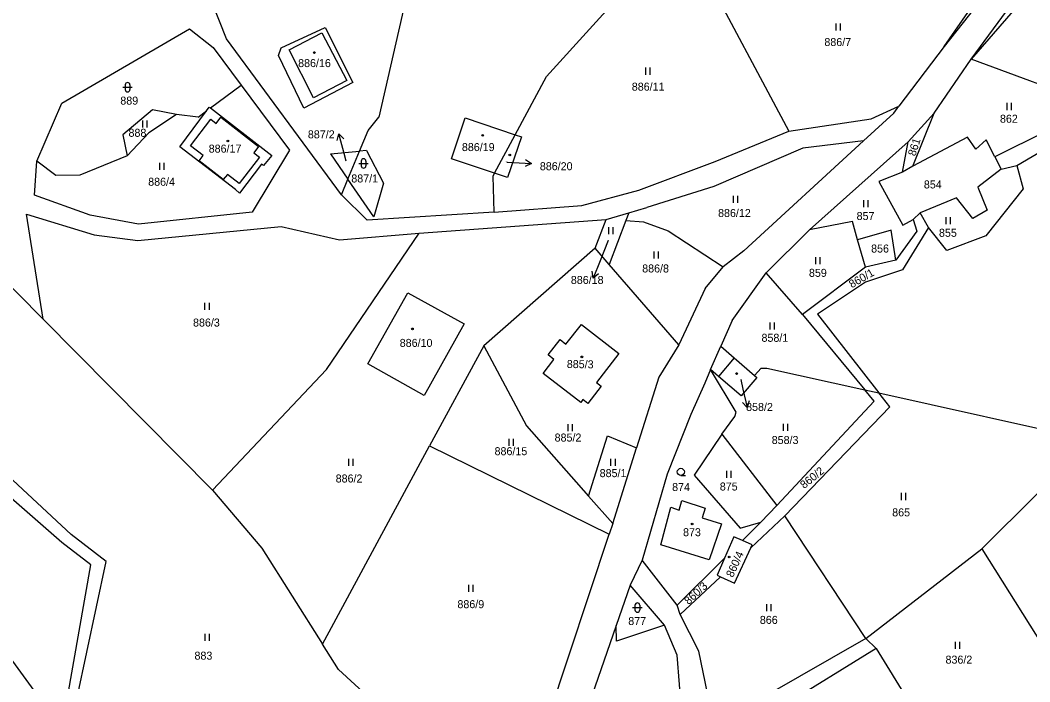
# Model space of a CAD drawing. Extents: x -670359 to -668019, y -978807 to -976674.
# Drawn here: x -669351.9 to -669137.4, y -977619.9 to -977479.4 of the extents above; entities that cross this region are included whole.
import ezdxf

# ---------------------------------------------------------------- set-up
doc = ezdxf.new("R2010")
doc.units = 0
for name, color, linetype in [('Hranice parcel', 7, 'Continuous'), ('Parcelní čísla', 7, 'Continuous'), ('Vnitřní kresba', 7, 'Continuous'), ('Značky budov', 7, 'Continuous'), ('Značky kultur', 7, 'Continuous')]:
    doc.layers.add(name, color=color, linetype=linetype)

msp = doc.modelspace()

# ---------------------------------------------------------------- linework, layer by layer
at = {"layer": 'Hranice parcel'}
for p, q in [((-669296.47, -977485.29), (-669287.14, -977480.93)), ((-669287.14, -977480.93), (-669281.27, -977492.61)), ((-669297.06, -977486.92), (-669296.47, -977485.29)), ((-669291.64, -977498.08), (-669297.06, -977486.92)), ((-669281.27, -977492.61), (-669291.64, -977498.08))]:
    msp.add_line(p, q, dxfattribs=at)
for points in [[(-669108.16, -977439.61), (-669149.88, -977487.66)], [(-669262.21, -977440.81), (-669275.7, -977499.98)], [(-669308.09, -977483.36), (-669317, -977460.78)], [(-669240.07, -977491.32), (-669212, -977460.35)], [(-669155.63, -977485.01), (-669142.12, -977465.6)], [(-669149.88, -977487.66), (-669133.84, -977465.83)], [(-669207.54, -977467.5), (-669188.62, -977502.97)], [(-669141.64, -977467.28), (-669155.63, -977485.01)], [(-669343.06, -977497.02), (-669315.95, -977481.19)], [(-669315.95, -977481.19), (-669310.92, -977485.22)], [(-669310.92, -977485.22), (-669305, -977493.18)], [(-669283.67, -977516.5), (-669308.09, -977483.36)], [(-669155.63, -977485.01), (-669165.21, -977497.66)], [(-669157.76, -977499.16), (-669149.88, -977487.66)], [(-669123.01, -977497.58), (-669149.88, -977487.66)], [(-669246.73, -977503.74), (-669240.07, -977491.32)], [(-669311.5, -977498.03), (-669305, -977493.18)], [(-669305, -977493.18), (-669294.73, -977507.01)], [(-669348.43, -977509.36), (-669343.06, -977497.02)], [(-669312.36, -977498.67), (-669311.75, -977497.84)], [(-669311.75, -977497.84), (-669311.5, -977498.03)], [(-669311.5, -977498.03), (-669298.5, -977508.1)], [(-669171.1, -977500.35), (-669165.21, -977497.66)], [(-669166.33, -977499.14), (-669165.21, -977497.66)], [(-669123.01, -977497.58), (-669144.82, -977508.4)], [(-669323.85, -977498.42), (-669330.14, -977503.73)], [(-669318.73, -977499.43), (-669324.63, -977503.3)], [(-669318.73, -977499.43), (-669323.85, -977498.42)], [(-669314.09, -977499.96), (-669318.73, -977499.43)], [(-669317.98, -977506.3), (-669312.36, -977498.67)], [(-669314.09, -977499.96), (-669312.36, -977498.67)], [(-669278.01, -977502.82), (-669275.7, -977499.98)], [(-669251.12, -977511.91), (-669260.28, -977508.84), (-669257.36, -977500.15)], [(-669257.36, -977500.15), (-669246.73, -977503.74)], [(-669166.33, -977499.14), (-669172.75, -977505.05)], [(-669163.23, -977505.23), (-669157.76, -977499.16)], [(-669162.29, -977510.43), (-669157.76, -977499.16)], [(-669140.19, -977510.25), (-669123.02, -977500.22)], [(-669188.62, -977502.97), (-669171.1, -977500.35)], [(-669330.14, -977503.73), (-669329.24, -977508.2)], [(-669324.63, -977503.3), (-669329.24, -977508.2)], [(-669279.84, -977507.23), (-669278.01, -977502.82)], [(-669251.12, -977511.91), (-669246.73, -977503.74)], [(-669246.73, -977503.74), (-669245.43, -977504.18), (-669248.36, -977512.84), (-669251.12, -977511.91)], [(-669204.3, -977509.42), (-669188.62, -977502.97)], [(-669150.65, -977504.22), (-669162.29, -977510.43)], [(-669148.9, -977506.79), (-669150.65, -977504.22)], [(-669306.22, -977515.38), (-669317.98, -977506.3)], [(-669185.65, -977506.58), (-669204.54, -977514.75)], [(-669198.14, -977528.41), (-669172.75, -977505.05)], [(-669172.75, -977505.05), (-669185.65, -977506.58)], [(-669184.19, -977523.89), (-669163.23, -977505.23)], [(-669164.45, -977511.7), (-669163.23, -977505.23)], [(-669146.65, -977504.79), (-669148.9, -977506.79)], [(-669144.82, -977508.4), (-669146.65, -977504.79)], [(-669329.24, -977508.2), (-669339.29, -977512.34)], [(-669294.73, -977507.01), (-669302.62, -977520.16)], [(-669298.5, -977508.1), (-669300.25, -977510.28)], [(-669285.98, -977507.78), (-669279.84, -977507.23)], [(-669285.98, -977507.78), (-669282.29, -977513.15)], [(-669282.29, -977513.15), (-669279.84, -977507.23)], [(-669278.38, -977507.1), (-669279.84, -977507.23)], [(-669278.38, -977507.1), (-669274.75, -977514.03)], [(-669144.82, -977508.4), (-669143.47, -977511.04)], [(-669348.91, -977516.54), (-669348.43, -977509.36)], [(-669344.33, -977512.37), (-669348.43, -977509.36)], [(-669300.64, -977509.97), (-669305.35, -977516.1)], [(-669300.25, -977510.28), (-669300.64, -977509.97)], [(-669220.45, -977515.51), (-669204.3, -977509.42)], [(-669162.29, -977510.43), (-669164.45, -977511.7)], [(-669143.47, -977511.04), (-669148.45, -977514.87)], [(-669143.47, -977511.04), (-669140.19, -977510.25)], [(-669140.19, -977510.25), (-669138.84, -977515.22)], [(-669339.29, -977512.34), (-669344.33, -977512.37)], [(-669283.67, -977516.5), (-669282.29, -977513.15)], [(-669276.79, -977521.15), (-669282.29, -977513.15)], [(-669251.43, -977512.49), (-669251.12, -977511.91)], [(-669251.24, -977520.17), (-669251.43, -977512.49)], [(-669164.45, -977511.7), (-669169.5, -977513.69)], [(-669274.75, -977514.03), (-669276.79, -977521.15)], [(-669204.54, -977514.75), (-669218.8, -977519.2)], [(-669169.5, -977513.69), (-669164.41, -977522.91)], [(-669148.45, -977514.87), (-669146.46, -977519.76)], [(-669138.84, -977515.22), (-669146.72, -977525.19)], [(-669337.08, -977520.79), (-669348.91, -977516.54)], [(-669305.35, -977516.1), (-669306.22, -977515.38)], [(-669278.22, -977521.9), (-669283.67, -977516.5)], [(-669232.6, -977518.73), (-669220.45, -977515.51)], [(-669153.02, -977517.1), (-669160.72, -977520.28)], [(-669149.51, -977521.51), (-669153.02, -977517.1)], [(-669251.24, -977520.17), (-669232.6, -977518.73)], [(-669222.6, -977520.3), (-669218.8, -977519.2)], [(-669347.06, -977542.92), (-669350.57, -977520.6)], [(-669350.57, -977520.6), (-669336.25, -977524.95)], [(-669326.83, -977522.73), (-669337.08, -977520.79)], [(-669302.62, -977520.16), (-669326.83, -977522.73)], [(-669251.24, -977520.17), (-669278.22, -977521.9)], [(-669267.17, -977524.66), (-669227.45, -977521.71)], [(-669229.76, -977527.85), (-669227.45, -977521.71)], [(-669227.45, -977521.71), (-669222.6, -977520.3)], [(-669222.6, -977520.3), (-669223.23, -977521.96)], [(-669164.41, -977522.91), (-669162.16, -977521.71)], [(-669160.72, -977520.28), (-669162.16, -977521.71)], [(-669162.16, -977521.71), (-669161.45, -977524.19)], [(-669158.97, -977523.4), (-669160.72, -977520.28)], [(-669146.46, -977519.76), (-669149.51, -977521.51)], [(-669326.97, -977526.2), (-669296.46, -977523.22)], [(-669296.46, -977523.22), (-669284.09, -977526.07)], [(-669223.23, -977521.96), (-669226.76, -977531.31)], [(-669223.23, -977521.96), (-669219.49, -977522.19)], [(-669219.49, -977522.19), (-669214.23, -977524.13)], [(-669193.43, -977533.07), (-669184.19, -977523.89)], [(-669175.05, -977522.16), (-669184.19, -977523.89)], [(-669174.03, -977526.08), (-669175.05, -977522.16)], [(-669158.97, -977523.4), (-669164.44, -977532.43)], [(-669155.06, -977528.29), (-669158.97, -977523.4)], [(-669336.25, -977524.95), (-669326.97, -977526.2)], [(-669286.84, -977553.62), (-669267.17, -977524.66)], [(-669284.09, -977526.07), (-669267.17, -977524.66)], [(-669214.23, -977524.13), (-669202.58, -977531.77)], [(-669166.89, -977524.02), (-669174.03, -977526.08)], [(-669165.87, -977530.34), (-669166.89, -977524.02)], [(-669161.45, -977524.19), (-669165.87, -977530.34)], [(-669146.72, -977525.19), (-669155.06, -977528.29)], [(-669363.13, -977526.7), (-669347.06, -977542.92)], [(-669229.76, -977527.85), (-669253.45, -977548.58)], [(-669226.76, -977531.31), (-669229.76, -977527.85)], [(-669172.29, -977531.84), (-669174.03, -977526.08)], [(-669198.14, -977528.41), (-669202.58, -977531.77)], [(-669165.87, -977530.34), (-669172.29, -977531.84)], [(-669211.97, -977548.38), (-669226.76, -977531.31)], [(-669206.41, -977536.39), (-669202.58, -977531.77)], [(-669172.29, -977531.84), (-669185.69, -977541.89)], [(-669164.44, -977532.43), (-669172.3, -977535.05)], [(-669200.67, -977543.21), (-669193.43, -977533.07)], [(-669185.69, -977541.89), (-669193.43, -977533.07)], [(-669206.41, -977536.39), (-669211.97, -977548.38)], [(-669172.3, -977535.05), (-669182.49, -977541.82)], [(-669278.06, -977552.4), (-669269.59, -977537.3)], [(-669269.59, -977537.3), (-669257.59, -977543.88)], [(-669311.1, -977579.22), (-669347.06, -977542.92)], [(-669200.67, -977543.21), (-669203.09, -977548.67)], [(-669185.69, -977541.89), (-669172.45, -977557.92)], [(-669182.49, -977541.82), (-669169.48, -977558.58)], [(-669257.59, -977543.88), (-669266.13, -977559.09)], [(-669236.01, -977548.19), (-669232.68, -977544.03)], [(-669232.68, -977544.03), (-669224.77, -977550.2)], [(-669239.77, -977550.48), (-669237.18, -977547.25)], [(-669237.18, -977547.25), (-669236.01, -977548.19)], [(-669253.45, -977548.58), (-669264.94, -977569.83)], [(-669253.45, -977548.58), (-669244.38, -977565.57)], [(-669211.97, -977548.38), (-669216.24, -977555.25)], [(-669205.27, -977553.6), (-669203.09, -977548.67)], [(-669203.09, -977548.67), (-669200.23, -977551.14)], [(-669240.79, -977554.44), (-669238.57, -977551.46)], [(-669238.57, -977551.46), (-669239.77, -977550.48)], [(-669224.77, -977550.2), (-669229.47, -977556.38)], [(-669200.23, -977551.14), (-669195.88, -977554.9)], [(-669311.1, -977579.22), (-669286.84, -977553.62)], [(-669266.13, -977559.09), (-669278.06, -977552.4)], [(-669205.27, -977553.6), (-669206.44, -977556.51)], [(-669199.77, -977562.65), (-669205.27, -977553.6)], [(-669203.55, -977555.07), (-669205.27, -977553.6)], [(-669195.88, -977554.9), (-669194.52, -977553.32)], [(-669194.52, -977553.32), (-669193.32, -977553.28)], [(-669193.32, -977553.28), (-669172.45, -977557.92)], [(-669232.83, -977560.61), (-669240.79, -977554.44)], [(-669216.24, -977555.25), (-669220.95, -977570.21)], [(-669198.76, -977559.21), (-669203.55, -977555.07)], [(-669195.4, -977555.31), (-669198.76, -977559.21)], [(-669195.88, -977554.9), (-669195.4, -977555.31)], [(-669228.49, -977557.16), (-669231.31, -977560.8)], [(-669229.47, -977556.38), (-669228.49, -977557.16)], [(-669206.44, -977556.51), (-669209.46, -977563.18)], [(-669170.46, -977560.33), (-669172.45, -977557.92)], [(-669172.45, -977557.92), (-669169.48, -977558.58)], [(-669232.36, -977559.99), (-669232.83, -977560.61)], [(-669231.31, -977560.8), (-669232.36, -977559.99)], [(-669191.19, -977582.52), (-669170.46, -977560.33)], [(-669167.18, -977561.54), (-669169.48, -977558.58)], [(-669169.48, -977558.58), (-669124.36, -977568.61)], [(-669167.18, -977561.54), (-669189.44, -977584.68)], [(-669341.12, -977588.67), (-669368.05, -977563.65)], [(-669209.46, -977563.18), (-669214.43, -977575.81)], [(-669202.83, -977567.36), (-669200.09, -977563.61)], [(-669200.09, -977563.61), (-669199.77, -977562.65)], [(-669343.11, -977590.36), (-669370.27, -977566.62)], [(-669244.38, -977565.57), (-669231.17, -977580.52)], [(-669231.17, -977580.52), (-669227.16, -977567.67)], [(-669227.16, -977567.67), (-669220.95, -977570.21)], [(-669202.83, -977567.36), (-669208.7, -977576.07)], [(-669202.83, -977567.36), (-669191.19, -977582.52)], [(-669147.59, -977591.68), (-669124.36, -977568.61)], [(-669287.69, -977611.91), (-669264.94, -977569.83)], [(-669264.94, -977569.83), (-669226.78, -977588.58)], [(-669226.03, -977586.34), (-669220.95, -977570.21)], [(-669214.43, -977575.81), (-669219.81, -977594.12)], [(-669208.7, -977576.07), (-669198.97, -977587.3)], [(-669311.1, -977579.22), (-669300.56, -977591.54)], [(-669226.03, -977586.34), (-669231.17, -977580.52)], [(-669211.93, -977583.5), (-669211.36, -977581.42)], [(-669211.36, -977581.42), (-669206.41, -977583.04)], [(-669215.8, -977590.85), (-669213.69, -977582.85)], [(-669213.69, -977582.85), (-669211.93, -977583.5)], [(-669206.41, -977583.04), (-669207.05, -977585.11)], [(-669194.57, -977586.03), (-669191.19, -977582.52)], [(-669207.05, -977585.11), (-669202.89, -977586.41)], [(-669198.97, -977587.3), (-669194.57, -977586.03)], [(-669194.57, -977586.03), (-669198.48, -977589.92)], [(-669189.44, -977584.68), (-669196.67, -977591.5)], [(-669172.23, -977610.73), (-669189.44, -977584.68)], [(-669226.03, -977586.34), (-669226.78, -977588.58)], [(-669202.89, -977586.41), (-669205.56, -977594)], [(-669336.93, -977595.11), (-669343.11, -977590.36)], [(-669333.65, -977594.37), (-669341.12, -977588.67)], [(-669239.62, -977627.27), (-669226.78, -977588.58)], [(-669200.29, -977589.11), (-669202.28, -977593.69)], [(-669198.48, -977589.92), (-669200.29, -977589.11)], [(-669196.37, -977590.86), (-669198.48, -977589.92)], [(-669300.56, -977591.54), (-669287.69, -977611.91)], [(-669205.56, -977594), (-669215.8, -977590.85)], [(-669200.17, -977599.01), (-669196.67, -977591.5)], [(-669196.67, -977591.5), (-669196.37, -977590.86)], [(-669172.23, -977610.73), (-669147.59, -977591.68)], [(-669147.59, -977591.68), (-669130.3, -977619.14)], [(-669339.81, -977623.26), (-669333.65, -977594.37)], [(-669219.81, -977594.12), (-669222.31, -977599.39)], [(-669212.32, -977603.66), (-669219.81, -977594.12)], [(-669202.28, -977593.69), (-669212.32, -977603.66)], [(-669202.28, -977593.69), (-669203.85, -977597.29)], [(-669347.25, -977624.1), (-669368.28, -977595.3)], [(-669341.89, -977623.27), (-669336.93, -977595.11)], [(-669203.16, -977597.61), (-669211.69, -977605.66)], [(-669203.85, -977597.29), (-669203.16, -977597.61)], [(-669203.16, -977597.61), (-669200.17, -977599.01)], [(-669222.31, -977599.39), (-669225.3, -977607.95)], [(-669215.06, -977607.89), (-669222.31, -977599.39)], [(-669211.69, -977605.66), (-669212.32, -977603.66)], [(-669207.71, -977613.43), (-669211.69, -977605.66)], [(-669225.3, -977607.95), (-669231.13, -977624.73)], [(-669225.24, -977611.31), (-669225.3, -977607.95)], [(-669215.06, -977607.89), (-669225.24, -977611.31)], [(-669212.35, -977614.3), (-669215.06, -977607.89)], [(-669172.23, -977610.73), (-669193.64, -977623)], [(-669172.23, -977610.73), (-669170.07, -977612.9)], [(-669284.27, -977617.33), (-669287.69, -977611.91)], [(-669204.48, -977629.2), (-669207.71, -977613.43)], [(-669170.07, -977612.9), (-669190.21, -977625.32)], [(-669170.07, -977612.9), (-669156.04, -977635.66)], [(-669210.82, -977632.95), (-669212.35, -977614.3)], [(-669284.27, -977617.33), (-669272.21, -977628.45)]]:
    msp.add_lwpolyline(points, dxfattribs=at)
at = {"layer": 'Parcelní čísla'}
for p, q in [((-669284.59, -977504.97), (-669284.2, -977503.52)), ((-669282.68, -977509.3), (-669283.18, -977507.39)), ((-669248.54, -977509.57), (-669247.29, -977509.63)), ((-669244.56, -977509), (-669243.29, -977509.8)), ((-669227.01, -977526.16), (-669228.73, -977530.48)), ((-669229.03, -977533.27), (-669230.2, -977534.2)), ((-669198.83, -977555.7), (-669198.36, -977557.78)), ((-669197.03, -977560.25), (-669197.47, -977561.68))]:
    msp.add_line(p, q, dxfattribs=at)
for points in [[(-669283.18, -977507.39), (-669284.2, -977503.52), (-669283.14, -977504.59)], [(-669247.29, -977509.63), (-669243.29, -977509.8), (-669244.62, -977510.5)], [(-669228.73, -977530.48), (-669230.2, -977534.2), (-669230.42, -977532.71)], [(-669198.36, -977557.78), (-669197.47, -977561.68), (-669198.49, -977560.58)]]:
    msp.add_lwpolyline(points, dxfattribs=at)
at = {"layer": 'Vnitřní kresba'}
for p, q in [((-669294.77, -977485.67), (-669287.81, -977482.08)), ((-669287.81, -977482.08), (-669282.5, -977492.21)), ((-669289.59, -977495.88), (-669294.77, -977485.67)), ((-669282.5, -977492.21), (-669289.59, -977495.88))]:
    msp.add_line(p, q, dxfattribs=at)
for points in [[(-669310.3, -977501.32), (-669309.3, -977500.02)], [(-669309.3, -977500.02), (-669301.3, -977506.22)], [(-669315.78, -977506.05), (-669311.46, -977500.43)], [(-669311.46, -977500.43), (-669310.3, -977501.32)], [(-669313.04, -977508.15), (-669315.78, -977506.05)], [(-669301.3, -977506.22), (-669302.3, -977507.56)], [(-669313.88, -977509.25), (-669313.04, -977508.15)], [(-669301.08, -977508.47), (-669305.42, -977514.09)], [(-669302.3, -977507.56), (-669301.08, -977508.47)], [(-669308.78, -977513.26), (-669313.88, -977509.25)], [(-669307.92, -977512.15), (-669308.78, -977513.26)], [(-669305.42, -977514.09), (-669307.92, -977512.15)], [(-669200.23, -977551.14), (-669203.55, -977555.07)]]:
    msp.add_lwpolyline(points, dxfattribs=at)
at = {"layer": 'Značky budov'}
for centre in [(-669289.43, -977486.26), (-669253.66, -977503.86), (-669307.8, -977505.04), (-669268.59, -977544.97), (-669232.58, -977550.91), (-669199.71, -977554.46), (-669209.16, -977586.41), (-669201.29, -977593.42)]:
    msp.add_circle(centre, 0.175, dxfattribs=at)
at = {"layer": 'Značky kultur'}
for p, q in [((-669178.62, -977480.06), (-669178.62, -977481.56)), ((-669177.62, -977481.56), (-669177.62, -977480.06)), ((-669219.1, -977489.46), (-669219.1, -977490.96)), ((-669218.1, -977490.96), (-669218.1, -977489.46)), ((-669330.11, -977493.63), (-669328.11, -977493.63)), ((-669329.61, -977493.13), (-669329.61, -977494.13)), ((-669328.61, -977493.13), (-669328.61, -977494.13)), ((-669142.32, -977496.97), (-669142.32, -977498.47)), ((-669141.32, -977498.47), (-669141.32, -977496.97)), ((-669325.93, -977500.67), (-669325.93, -977502.17)), ((-669324.93, -977502.17), (-669324.93, -977500.67)), ((-669322.35, -977509.67), (-669322.35, -977511.17)), ((-669321.35, -977511.17), (-669321.35, -977509.67)), ((-669279.97, -977509.82), (-669277.97, -977509.82)), ((-669279.47, -977509.32), (-669279.47, -977510.32)), ((-669278.47, -977509.32), (-669278.47, -977510.32)), ((-669200.43, -977516.69), (-669200.43, -977518.19)), ((-669199.43, -977518.19), (-669199.43, -977516.69)), ((-669172.78, -977517.63), (-669172.78, -977519.13)), ((-669171.78, -977519.13), (-669171.78, -977517.63)), ((-669155.28, -977521.2), (-669155.28, -977522.7)), ((-669154.28, -977522.7), (-669154.28, -977521.2)), ((-669226.94, -977523.37), (-669226.94, -977524.87)), ((-669225.94, -977524.87), (-669225.94, -977523.37)), ((-669217.32, -977528.52), (-669217.32, -977530.02)), ((-669216.32, -977530.02), (-669216.32, -977528.52)), ((-669182.95, -977529.71), (-669182.95, -977531.21)), ((-669181.95, -977531.21), (-669181.95, -977529.71)), ((-669312.74, -977539.45), (-669312.74, -977540.95)), ((-669311.74, -977540.95), (-669311.74, -977539.45)), ((-669192.65, -977543.63), (-669192.65, -977545.13)), ((-669191.65, -977545.13), (-669191.65, -977543.63)), ((-669235.56, -977565.18), (-669235.56, -977566.68)), ((-669234.56, -977566.68), (-669234.56, -977565.18)), ((-669189.85, -977565.13), (-669189.85, -977566.63)), ((-669188.85, -977566.63), (-669188.85, -977565.13)), ((-669248.13, -977568.29), (-669248.13, -977569.79)), ((-669247.13, -977569.79), (-669247.13, -977568.29)), ((-669282.15, -977572.59), (-669282.15, -977574.09)), ((-669281.15, -977574.09), (-669281.15, -977572.59)), ((-669226.47, -977572.57), (-669226.47, -977574.07)), ((-669225.47, -977574.07), (-669225.47, -977572.57)), ((-669201.85, -977575.1), (-669201.85, -977576.6)), ((-669200.85, -977576.6), (-669200.85, -977575.1)), ((-669211.56, -977576.09), (-669210.56, -977576.09)), ((-669164.75, -977579.83), (-669164.75, -977581.33)), ((-669163.75, -977581.33), (-669163.75, -977579.83)), ((-669256.69, -977599.32), (-669256.69, -977600.82)), ((-669255.69, -977600.82), (-669255.69, -977599.32)), ((-669221.8, -977604.18), (-669219.8, -977604.18)), ((-669221.3, -977603.68), (-669221.3, -977604.68)), ((-669220.3, -977603.68), (-669220.3, -977604.68)), ((-669193.38, -977603.44), (-669193.38, -977604.94)), ((-669192.38, -977604.94), (-669192.38, -977603.44)), ((-669312.68, -977609.73), (-669312.68, -977611.23)), ((-669311.68, -977611.23), (-669311.68, -977609.73)), ((-669153.27, -977611.46), (-669153.27, -977612.96)), ((-669152.27, -977612.96), (-669152.27, -977611.46))]:
    msp.add_line(p, q, dxfattribs=at)
for centre, radius in [((-669289.43, -977486.26), 0.175), ((-669253.66, -977503.86), 0.175), ((-669307.8, -977505.04), 0.175), ((-669247.9, -977508.02), 0.175), ((-669268.59, -977544.97), 0.175), ((-669232.58, -977550.91), 0.175), ((-669199.71, -977554.46), 0.175), ((-669211.56, -977575.34), 0.75), ((-669209.16, -977586.41), 0.175), ((-669201.29, -977593.42), 0.175)]:
    msp.add_circle(centre, radius, dxfattribs=at)
for centre, start, end in [((-669329.11, -977493.13), 0, 180), ((-669329.11, -977494.13), 180, 0), ((-669278.97, -977509.32), 0, 180), ((-669278.97, -977510.32), 180, 0), ((-669220.8, -977603.68), 0, 180), ((-669220.8, -977604.68), 180, 0)]:
    msp.add_arc(centre, 0.5, start, end, dxfattribs=at)

# ---------------------------------------------------------------- texts
at = {"layer": 'Parcelní čísla'}
for s, height, p in [('886/7', 1.7, (-669181.06, -977484.88)), ('886/16', 1.7, (-669292.88, -977489.35)), ('886/11', 1.7, (-669221.98, -977494.36)), ('889', 1.7, (-669330.66, -977497.32)), ('862', 1.7, (-669143.75, -977501.17)), ('888', 1.7, (-669328.92, -977504.16)), ('887/2', 1.7, (-669290.81, -977504.49)), ('886/17', 1.7, (-669311.88, -977507.52)), ('886/19', 1.7, (-669258.08, -977507.19)), ('887/2', 0.1, (-669282.68, -977509.3)), ('886/20', 0.1, (-669248.78, -977509.57)), ('886/20', 1.7, (-669241.52, -977511.26)), ('886/4', 1.7, (-669324.74, -977514.56)), ('887/1', 1.7, (-669281.58, -977513.86)), ('854', 1.7, (-669159.92, -977515.13)), ('886/12', 1.7, (-669203.65, -977521.2)), ('857', 1.7, (-669174.21, -977521.83)), ('855', 1.7, (-669156.71, -977525.4)), ('886/18', 0.1, (-669227.25, -977526.16)), ('856', 1.7, (-669171.13, -977528.75)), ('886/8', 1.7, (-669219.77, -977532.98)), ('859', 1.7, (-669184.34, -977533.91)), ('886/18', 1.7, (-669234.93, -977535.42)), ('886/3', 1.7, (-669315.21, -977544.47)), ('886/10', 1.7, (-669271.29, -977548.79)), ('858/1', 1.7, (-669194.42, -977547.71)), ('858/2', 0.1, (-669198.83, -977555.7)), ('858/2', 1.7, (-669197.69, -977562.4)), ('885/2', 1.7, (-669238.38, -977568.9)), ('858/3', 1.7, (-669192.25, -977569.42)), ('886/15', 1.7, (-669251.14, -977571.8)), ('885/1', 1.7, (-669228.81, -977576.46)), ('886/2', 1.7, (-669284.9, -977577.6)), ('874', 1.7, (-669213.41, -977579.41)), ('875', 1.7, (-669203.28, -977579.3)), ('865', 1.7, (-669166.65, -977584.8)), ('873', 1.7, (-669211.09, -977589.01)), ('886/9', 1.7, (-669259.03, -977604.3)), ('877', 1.7, (-669222.73, -977607.88)), ('866', 1.7, (-669194.77, -977607.64)), ('883', 1.7, (-669314.9, -977615.23)), ('836/2', 1.7, (-669155.32, -977616.08))]:
    msp.add_text(s, height=height, dxfattribs=at).set_placement(p)
for s, rotation, p in [('861', 72.1201, (-669161.75, -977508.38)), ('860/1', 30.0029, (-669175.23, -977536.36)), ('885/3', 359.1235, (-669235.8, -977553.27)), ('860/2', 39.0938, (-669185.36, -977579.02)), ('860/4', 65.5533, (-669200.5, -977597.89)), ('860/3', 42.9432, (-669209.9, -977603.67))]:
    msp.add_text(s, height=1.7, rotation=rotation, dxfattribs=at).set_placement(p)

doc.saveas('drawing.dxf')
